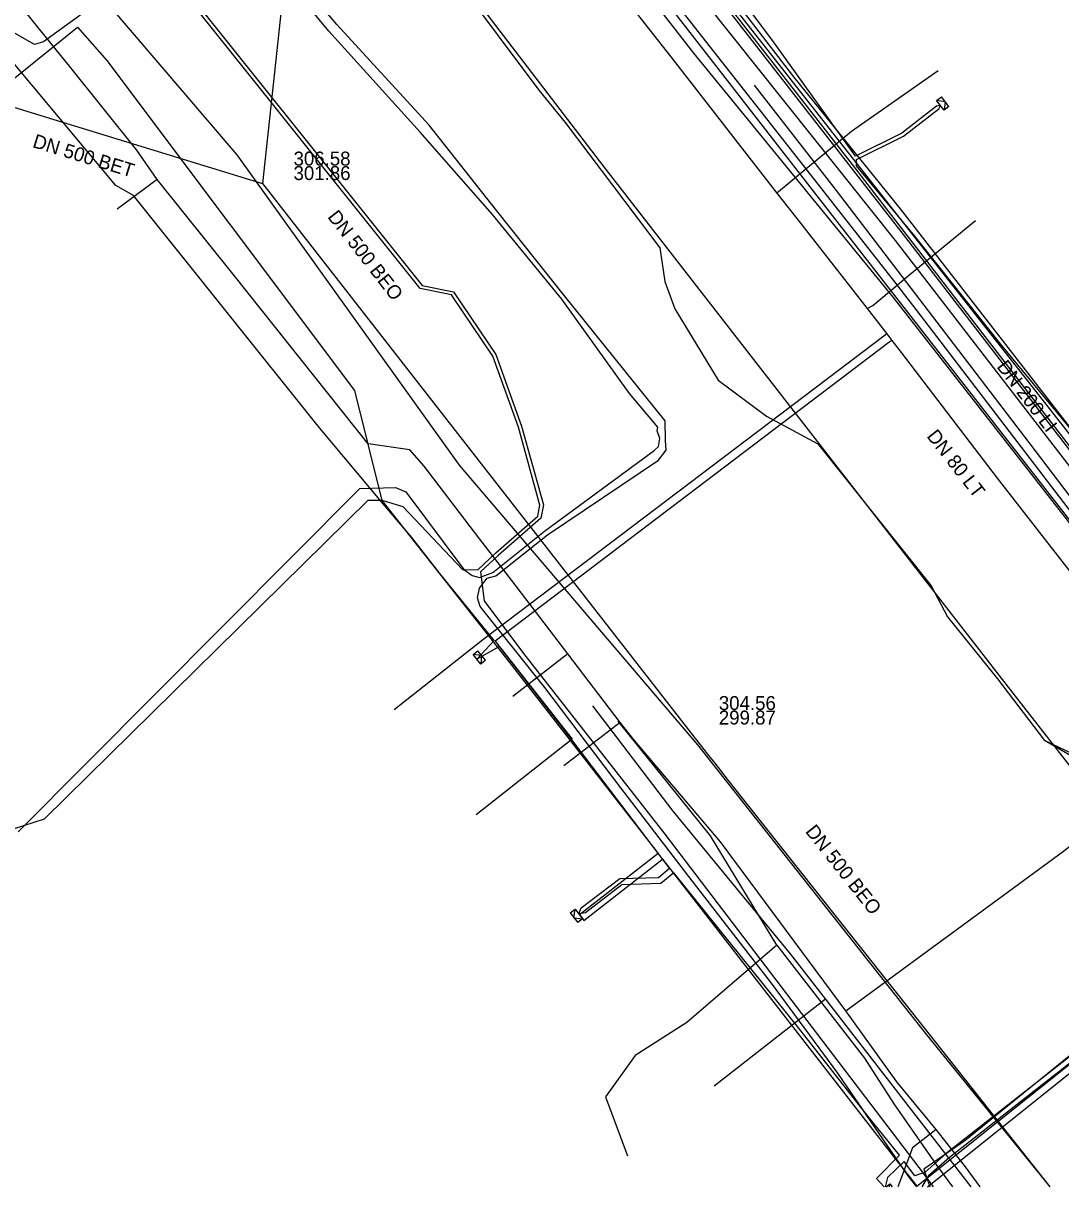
# Model space of a CAD drawing. Extents: x -600391 to -599491, y -1160176 to -1159402.
# Drawn here: x -600242.3 to -600182.8, y -1160176.1 to -1160109.3 of the extents above; entities that cross this region are included whole.
import ezdxf

# ---------------------------------------------------------------- set-up
doc = ezdxf.new("R2010")
doc.units = 0
for name, color, linetype in [('31', 7, 'Continuous'), ('CETIN_linie', 7, 'Continuous'), ('Vrstva 12', 7, 'Continuous'), ('Vrstva 13', 7, 'Continuous'), ('Vrstva 15', 7, 'Continuous'), ('Vrstva 16', 7, 'Continuous'), ('Vrstva 19', 7, 'Continuous'), ('Vrstva 42', 7, 'Continuous'), ('Vrstva 43', 7, 'Continuous'), ('Vrstva 44', 7, 'Continuous'), ('Vrstva 55', 7, 'Continuous'), ('Vrstva 58', 7, 'Continuous'), ('Vrstva 9', 7, 'Continuous')]:
    doc.layers.add(name, color=color, linetype=linetype)

# ---------------------------------------------------------------- blocks, each defined once
blk = doc.blocks.new('NN630')
at = {"layer": '31'}
for points in [[(0, -0.7), (-0.7, 0)], [(-0.7, -0.7), (-0.7, 0), (0.7, 0), (0.7, -0.7)], [(-0.7, -0.7), (0.7, -0.7)], [(0, -0.7), (0.7, 0)]]:
    blk.add_lwpolyline(points, dxfattribs=at)

msp = doc.modelspace()

# ---------------------------------------------------------------- linework, layer by layer
at = {"layer": 'CETIN_linie'}
for p, q in [((-600208.44, -1160099.88), (-600194.75, -1160117.41)), ((-600202.68, -1160170.29), (-600196.29, -1160165.3))]:
    msp.add_line(p, q, dxfattribs=at)
for points in [[(-600267.76, -1160025.17), (-600244.25, -1160055.86), (-600225.67, -1160079.89), (-600215.81, -1160092.29), (-600192.29, -1160121.78), (-600180.19, -1160137.43), (-600168.62, -1160151.9), (-600165.36, -1160149.31), (-600163.31, -1160147.71)], [(-600225.43, -1160097.28), (-600224.31, -1160097.79), (-600223.76, -1160098.18), (-600216.62, -1160107.61), (-600209.03, -1160117.53), (-600185.54, -1160147.75), (-600167.22, -1160171.18)], [(-600236.95, -1160106.39), (-600225.2, -1160098.31), (-600224.42, -1160098.02), (-600223.61, -1160098.65), (-600217.59, -1160106.66), (-600212.75, -1160113.15), (-600211.24, -1160114.99), (-600205.8, -1160122.19), (-600205.52, -1160124.13), (-600204.93, -1160125.7), (-600202.44, -1160129.78), (-600199.68, -1160131.86), (-600196.72, -1160133.45), (-600190.22, -1160141.6), (-600189.29, -1160143.37), (-600186.42, -1160146.92), (-600183.71, -1160150.47)], [(-600236.72, -1160106.71), (-600237.57, -1160107.73), (-600241.19, -1160110.36), (-600241.71, -1160110.53), (-600244.04, -1160109.21), (-600244.88, -1160109.24), (-600251.06, -1160114.23), (-600251.34, -1160113.88), (-600256.71, -1160110.78), (-600256.89, -1160110.66)], [(-600180.83, -1160138.31), (-600184.6, -1160133.37), (-600195.65, -1160118.9), (-600200.37, -1160112.86)], [(-600194.75, -1160117.41), (-600192.3, -1160120.58), (-600180.04, -1160136.48), (-600176.68, -1160141), (-600173.44, -1160144.95)], [(-600174.41, -1160145.12), (-600174.77, -1160147.05), (-600180.97, -1160152.06), (-600183.71, -1160150.47)], [(-600174.41, -1160145.12), (-600175.38, -1160146.58), (-600181.31, -1160151.62), (-600183.71, -1160150.47)], [(-600196.29, -1160165.3), (-600198.29, -1160162.72), (-600205.03, -1160154.52), (-600209.65, -1160148.48)], [(-600199.08, -1160162.22), (-600202.89, -1160155.93), (-600208.19, -1160149.36)], [(-600199.08, -1160162.22), (-600204.25, -1160166.66), (-600207.22, -1160168.54), (-600208.92, -1160170.91), (-600207.66, -1160174.31)], [(-600199.08, -1160162.22), (-600194.04, -1160168.7), (-600192.37, -1160171.33), (-600189.95, -1160174.79), (-600188.987, -1160176.079)], [(-600187.931, -1160176.079), (-600191.8, -1160171.08), (-600196.29, -1160165.3)]]:
    msp.add_lwpolyline(points, dxfattribs=at)
at = {"layer": 'Vrstva 13'}
for points in [[(-600224.89, -1160086.22), (-600223.66, -1160087.79), (-600219.48, -1160093.03), (-600208.78, -1160106.62), (-600205.17, -1160111.23), (-600199.082, -1160119.045), (-600197.73, -1160120.78), (-600193.89, -1160125.68), (-600192.77, -1160127.135), (-600192.48, -1160127.51), (-600191.95, -1160128.2), (-600186.44, -1160135.41), (-600179, -1160144.94), (-600171.696, -1160154.271), (-600171.65, -1160154.33), (-600167.97, -1160159.08), (-600165.22, -1160162.741), (-600160.551, -1160168.918), (-600159.86, -1160169.84), (-600157.58, -1160168), (-600157.9, -1160167.54)], [(-600219.33, -1160089.71), (-600216.29, -1160093.64), (-600198.339, -1160116.482), (-600192.274, -1160124.216), (-600191.1, -1160125.733), (-600170.22, -1160153.004), (-600164.3, -1160160.4), (-600163.344, -1160161.593), (-600158.656, -1160167.697)], [(-600199.082, -1160119.045), (-600198.98, -1160118.96), (-600197.411, -1160117.666), (-600194.792, -1160115.491), (-600189.816, -1160112.008)], [(-600193.89, -1160125.68), (-600193.569, -1160125.51), (-600192.181, -1160124.336), (-600191.76, -1160123.98), (-600187.674, -1160120.626)], [(-600192.77, -1160127.135), (-600192.929, -1160127.256), (-600215.89, -1160144.63), (-600221.054, -1160148.699)], [(-600192.48, -1160127.51), (-600192.643, -1160127.627), (-600215.258, -1160144.762), (-600210.84, -1160150.39), (-600216.345, -1160154.726)]]:
    msp.add_lwpolyline(points, dxfattribs=at)
at = {"layer": 'Vrstva 16'}
msp.add_lwpolyline([(-600149.134, -1160176.079), (-600149.77, -1160175.26), (-600153.28, -1160170.92), (-600160.82, -1160161.59), (-600162.37, -1160159.57), (-600191.81, -1160121.42), (-600215.03, -1160091.66), (-600218.37, -1160087.39), (-600241.27, -1160058.04), (-600268.45, -1160023.15), (-600268.66, -1160022.86), (-600279.96, -1160008.45), (-600285.15, -1160001.76), (-600292.76, -1159991.95), (-600306.26, -1159974.55), (-600310.89, -1159968.58), (-600323.17, -1159952.95), (-600331.19, -1159942.75), (-600331.3, -1159942.61), (-600336.91, -1159935.47), (-600352.95, -1159915.04), (-600356.32, -1159910.78), (-600372.09, -1159890.83), (-600376.451, -1159885.301)], dxfattribs=at)
at = {"layer": 'Vrstva 19'}
for points in [[(-600187.404, -1160176.079), (-600188.24, -1160174.94), (-600189.714, -1160173.065), (-600189.932, -1160172.795), (-600192.198, -1160170.051), (-600195.116, -1160165.979), (-600202.322, -1160156.29), (-600207.254, -1160150.47), (-600208.079, -1160149.427), (-600211.081, -1160145.492), (-600214.3, -1160141.284), (-600216.14, -1160138.91), (-600219.326, -1160134.724), (-600220.15, -1160133.78), (-600222.55, -1160133.45), (-600230.24, -1160123.78), (-600234.667, -1160118.276), (-600235.82, -1160116.58), (-600239.7, -1160111.77), (-600241.589, -1160109.434), (-600248.735, -1160100.513)], [(-600234.667, -1160118.276), (-600236.957, -1160119.973)], [(-600211.081, -1160145.492), (-600214.234, -1160147.942)], [(-600208.079, -1160149.427), (-600211.303, -1160151.926)], [(-600195.116, -1160165.979), (-600182.616, -1160156.82), (-600181.911, -1160156.255), (-600181.637, -1160156.017), (-600181.34, -1160155.787)], [(-600189.932, -1160172.795), (-600191.295, -1160173.84), (-600192.126, -1160176.079)]]:
    msp.add_lwpolyline(points, dxfattribs=at)
at = {"layer": 'Vrstva 42'}
for points in [[(-600181.09, -1160133.93), (-600186.24, -1160127.71), (-600191.15, -1160121.53), (-600194.5, -1160117.48), (-600194.508, -1160117.12), (-600191.807, -1160115.785), (-600189.787, -1160114.222), (-600189.69, -1160114.02), (-600189.91, -1160114.064), (-600191.913, -1160115.615), (-600194.569, -1160116.928), (-600199.31, -1160110.32), (-600202.9, -1160105.51)], [(-600246.552, -1160115.414), (-600239.241, -1160109.519), (-600237.541, -1160111.431), (-600223.338, -1160130.385), (-600221.756, -1160136.694), (-600216.842, -1160142.929), (-600214.427, -1160145.992), (-600205.901, -1160156.959), (-600210.402, -1160160.475), (-600210.279, -1160160.633), (-600210.156, -1160160.791), (-600205.655, -1160157.275), (-600192.327, -1160174.418), (-600191.04, -1160176.052), (-600174.619, -1160162.942), (-600174.457, -1160161.146), (-600168.134, -1160156.095), (-600166.808, -1160156.146), (-600165.41, -1160155.108), (-600162.138, -1160159.429), (-600158.651, -1160156.892), (-600155.694, -1160159.162), (-600151.097, -1160155.641), (-600151.957, -1160154.573)], [(-600192.913, -1160176.079), (-600193.364, -1160175.599), (-600192.035, -1160174.268), (-600193.831, -1160172.039), (-600197.888, -1160166.885), (-600204.998, -1160158.063), (-600205.746, -1160158.667), (-600207.973, -1160158.752), (-600210.075, -1160160.353), (-600210.451, -1160160.423), (-600210.306, -1160160.071), (-600208.097, -1160158.393), (-600205.875, -1160158.337), (-600205.241, -1160157.8), (-600211.384, -1160149.729), (-600215.003, -1160145.076), (-600216.302, -1160145.806), (-600215.309, -1160144.724), (-600218.439, -1160140.88), (-600220.044, -1160138.819), (-600221.692, -1160136.886), (-600225.407, -1160132.425), (-600236.02, -1160119.197), (-600237.029, -1160118.606), (-600243.522, -1160110.856)], [(-600190.433, -1160176.079), (-600174.235, -1160163.148), (-600174.073, -1160161.352), (-600168, -1160156.501), (-600166.682, -1160156.552), (-600165.49, -1160155.666), (-600162.22, -1160159.983), (-600158.658, -1160157.391), (-600155.694, -1160159.666), (-600150.529, -1160155.71), (-600151.639, -1160154.329)], [(-600181.04, -1160167.655), (-600189.363, -1160174.167), (-600190.556, -1160175.242), (-600191.156, -1160175.461), (-600191.773, -1160174.63), (-600192.728, -1160175.554), (-600192.852, -1160176.079)], [(-600180.86, -1160167.895), (-600189.172, -1160174.399), (-600190.375, -1160175.444), (-600190.756, -1160176.079)]]:
    msp.add_lwpolyline(points, dxfattribs=at)
at = {"layer": 'Vrstva 43'}
msp.add_line((-600192.609, -1160176.079), (-600192.589, -1160175.917), dxfattribs=at)
msp.add_lwpolyline([(-600192.797, -1160176.079), (-600192.589, -1160175.917), (-600192.463, -1160176.079)], dxfattribs=at)
at = {"layer": 'Vrstva 44'}
for points in [[(-600160.621, -1160151.483), (-600164.61, -1160154.49), (-600164.75, -1160154.55), (-600164.92, -1160154.53), (-600165.13, -1160154.43), (-600167.52, -1160151.31), (-600171.43, -1160146.29), (-600175.79, -1160140.75), (-600179.33, -1160136.25), (-600182.1, -1160132.67), (-600186.25, -1160127.32), (-600191.99, -1160119.95), (-600198.1, -1160112.38), (-600204.78, -1160103.69), (-600209.2, -1160098.08), (-600214.66, -1160091.39), (-600216.44, -1160089.98), (-600217.86, -1160088.43), (-600221.95, -1160082.93), (-600222.23, -1160082.56), (-600222.64, -1160080.93), (-600222.7, -1160080.75), (-600225.12, -1160077.51), (-600230.17, -1160070.83)], [(-600242.63, -1160155.71), (-600223.03, -1160136.01), (-600220.97, -1160135.94), (-600220.38, -1160136.2), (-600217.06, -1160140.66), (-600216.58, -1160141), (-600216.16, -1160141.12), (-600215.39, -1160140.83), (-600212.419, -1160138.452), (-600206.12, -1160133.83), (-600205.884, -1160133.585), (-600205.79, -1160133.14), (-600205.95, -1160132.69), (-600205.91, -1160132.49), (-600207.54, -1160130.56), (-600211.43, -1160125.14), (-600215.4, -1160120.28), (-600219.56, -1160115.55), (-600224.8, -1160109.76), (-600230.36, -1160103.04), (-600233.16, -1160099.57), (-600236.83, -1160094.8), (-600238.73, -1160092.17), (-600250.56, -1160076.56)], [(-600215.22, -1160141.01), (-600212.24, -1160138.67), (-600205.87, -1160134.37), (-600205.43, -1160133.8), (-600205.48, -1160133.24), (-600205.5, -1160132.12), (-600211.27, -1160124.94), (-600215.15, -1160120.07), (-600219.05, -1160115.15), (-600224.34, -1160109.38), (-600229.81, -1160102.89), (-600232.83, -1160099.34), (-600236.52, -1160094.54), (-600238.5, -1160091.97), (-600249.74, -1160077.1)], [(-600242.907, -1160155.529), (-600241.127, -1160154.969), (-600222.537, -1160136.669), (-600221.757, -1160136.679), (-600220.547, -1160137.039), (-600217.127, -1160140.649), (-600216.251, -1160140.666), (-600215.214, -1160139.705), (-600212.809, -1160137.597), (-600212.69, -1160136.953), (-600213.922, -1160132.479), (-600215.387, -1160128.415), (-600217.767, -1160124.889), (-600219.562, -1160124.53), (-600235.699, -1160104.336), (-600236.662, -1160102.721), (-600240.31, -1160096.813), (-600240.038, -1160094.179), (-600240.194, -1160092.788), (-600242.277, -1160088.713), (-600243.305, -1160086.547)], [(-600243.129, -1160086.451), (-600242.097, -1160088.625), (-600240, -1160092.73), (-600239.836, -1160094.179), (-600240.104, -1160096.765), (-600236.492, -1160102.617), (-600235.535, -1160104.222), (-600219.452, -1160124.348), (-600217.647, -1160124.709), (-600215.207, -1160128.323), (-600213.732, -1160132.419), (-600212.484, -1160136.945), (-600212.625, -1160137.701), (-600215.08, -1160139.853), (-600216.092, -1160140.791), (-600215.887, -1160142.459), (-600213.627, -1160145.479), (-600205.577, -1160155.769), (-600190.627, -1160175.369), (-600190.098, -1160176.079)], [(-600191.039, -1160176.079), (-600191.54, -1160175.45), (-600195.57, -1160169.57), (-600199.38, -1160164.39), (-600203.95, -1160158.52), (-600208.04, -1160153.19), (-600212.41, -1160147.42), (-600216.12, -1160142.77), (-600216.26, -1160142.27), (-600216.15, -1160141.73), (-600215.72, -1160141.15), (-600215.22, -1160141.01)]]:
    msp.add_lwpolyline(points, dxfattribs=at)
at = {"layer": 'Vrstva 55'}
for points in [[(-600159.37, -1160161.02), (-600163.57, -1160162.94), (-600178.28, -1160142.933), (-600197.299, -1160118.521), (-600212.697, -1160098.724), (-600214.119, -1160096.9), (-600217.08, -1160091.68), (-600222.93, -1160082.91), (-600226.85, -1160080.74), (-600230.45, -1160076.02), (-600247.641, -1160053.846), (-600267.85, -1160028.08), (-600281.812, -1160010.273), (-600299.508, -1159987.183)], [(-600159.37, -1160161.02), (-600162.95, -1160162.67), (-600163.57, -1160162.94), (-600178.36, -1160142.986), (-600192.39, -1160125.04), (-600203.84, -1160111.02), (-600214.66, -1160097.11), (-600217.08, -1160091.68), (-600222.93, -1160082.91), (-600226.85, -1160080.74), (-600230.45, -1160076.02), (-600230.45, -1160076.94), (-600237.55, -1160083.37), (-600235.29, -1160086.88), (-600234.96, -1160088.55), (-600235.88, -1160090.06), (-600243.77, -1160096.03)], [(-600183.385, -1160176.079), (-600190.519, -1160167.28), (-600203.613, -1160150.715), (-600217.299, -1160134.673), (-600230.074, -1160116.863), (-600237.553, -1160108.104), (-600237.57, -1160106.07), (-600236.65, -1160103.88), (-600235.511, -1160102.748)]]:
    msp.add_lwpolyline(points, dxfattribs=at)
at = {"layer": 'Vrstva 58'}
for points in [[(-600152.816, -1160155.247), (-600149.861, -1160159.292), (-600149.734, -1160159.861), (-600149.948, -1160160.271), (-600152.824, -1160162.001), (-600154.716, -1160162.875), (-600156.47, -1160162.913), (-600156.971, -1160162.768), (-600158.029, -1160162.46), (-600159.391, -1160161.608), (-600159.936, -1160160.912), (-600162.585, -1160157.659), (-600164.043, -1160155.634), (-600165.021, -1160154.824), (-600214.84, -1160091.439), (-600216.589, -1160090.02), (-600218.109, -1160088.272), (-600222.441, -1160082.519), (-600222.948, -1160080.77), (-600256.663, -1160038.315), (-600300.347, -1159981.753)], [(-600153.003, -1160155.509), (-600149.65, -1160160.166), (-600149.735, -1160160.405), (-600155.82, -1160163.89), (-600157.66, -1160163.53), (-600160.562, -1160160.656), (-600164.66, -1160155.26), (-600165.9, -1160155.35), (-600173.46, -1160161.49), (-600181.19, -1160167.69), (-600188.29, -1160173.44), (-600190.64, -1160175.07), (-600190.288, -1160176.079)]]:
    msp.add_lwpolyline(points, dxfattribs=at)
at = {"layer": 'Vrstva 9'}
msp.add_line((-600225.57, -1160090.33), (-600228.619, -1160118.508), dxfattribs=at)
for points in [[(-600252.771, -1160111.047), (-600249.473, -1160112.088), (-600241.091, -1160114.668), (-600228.619, -1160118.508)], [(-600228.619, -1160118.508), (-600210.086, -1160142.245), (-600202.996, -1160151.325), (-600202.645, -1160151.775), (-600201.876, -1160152.76)], [(-600201.876, -1160152.76), (-600191.292, -1160166.119), (-600183.402, -1160176.079)]]:
    msp.add_lwpolyline(points, dxfattribs=at)

# ---------------------------------------------------------------- block references
at = {"layer": 'Vrstva 43', "xscale": 0.5, "yscale": 0.5}
for p, rotation in [((-600189.69, -1160114.021), 128), ((-600216.302, -1160145.806), 129), ((-600210.451, -1160160.423), -52.000000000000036)]:
    msp.add_blockref('NN630', p, dxfattribs=dict(at, rotation=rotation))

# ---------------------------------------------------------------- texts
at = {"layer": 'Vrstva 12'}
for s, rotation, p in [('DN 500 BET', 342.91524, (-600241.86, -1160116.404)), ('DN 500 BEO', 307.96481, (-600224.913, -1160120.423)), ('DN 500 BEO', 308.36589, (-600197.481, -1160155.697))]:
    msp.add_text(s, height=0.8, rotation=rotation, dxfattribs=at).set_placement(p)
for s, p in [('306.58', (-600226.829, -1160117.469)), ('301.86', (-600226.829, -1160118.301)), ('304.56', (-600202.411, -1160148.719)), ('299.87', (-600202.411, -1160149.551))]:
    msp.add_text(s, height=0.8, dxfattribs=at).set_placement(p)
at = {"layer": 'Vrstva 15'}
for s, rotation, p in [('DN 200 LI', 307.44915, (-600186.491, -1160129.024)), ('DN 80 LT', 307.96481, (-600190.513, -1160133.01))]:
    msp.add_text(s, height=0.8, rotation=rotation, dxfattribs=at).set_placement(p)

doc.saveas('drawing.dxf')
